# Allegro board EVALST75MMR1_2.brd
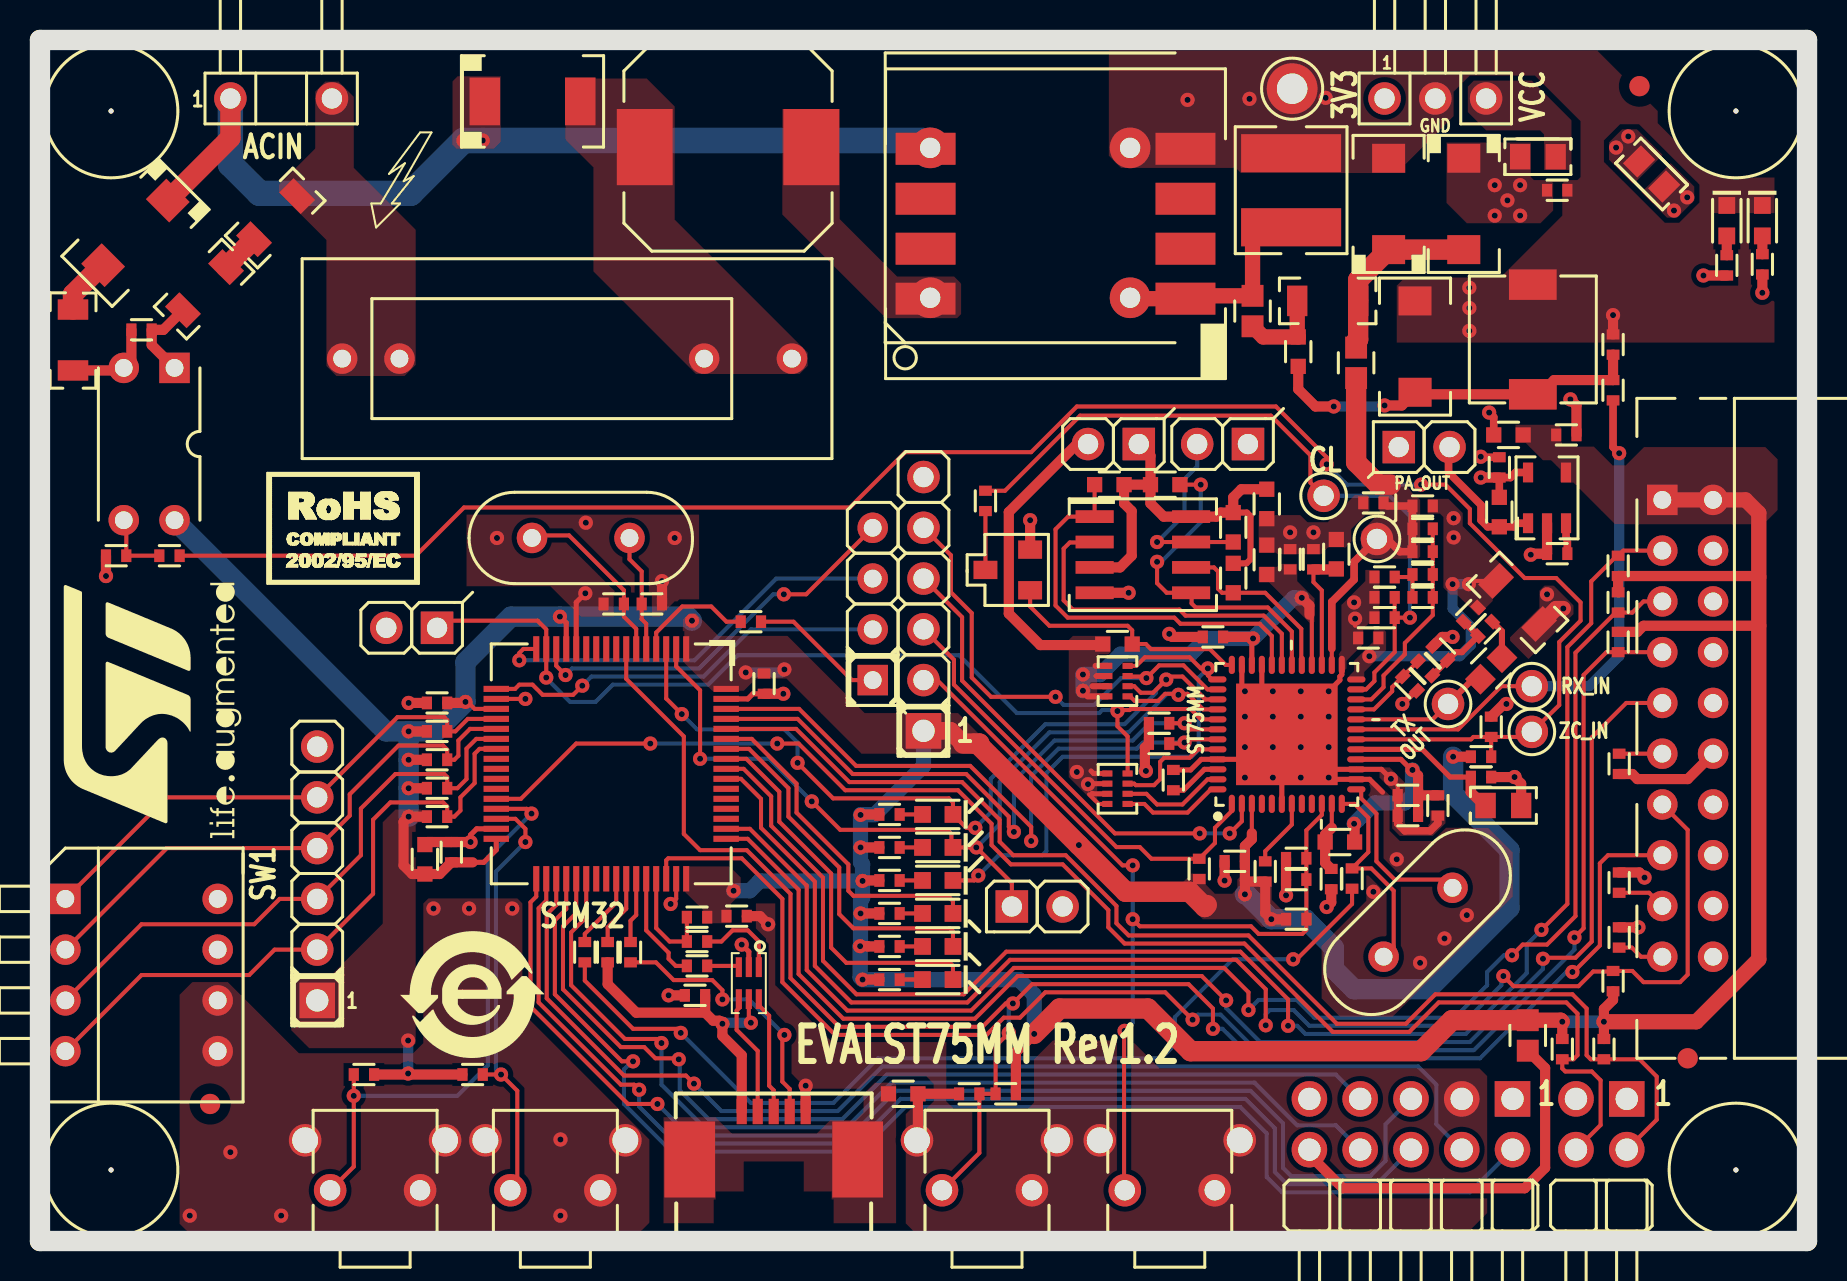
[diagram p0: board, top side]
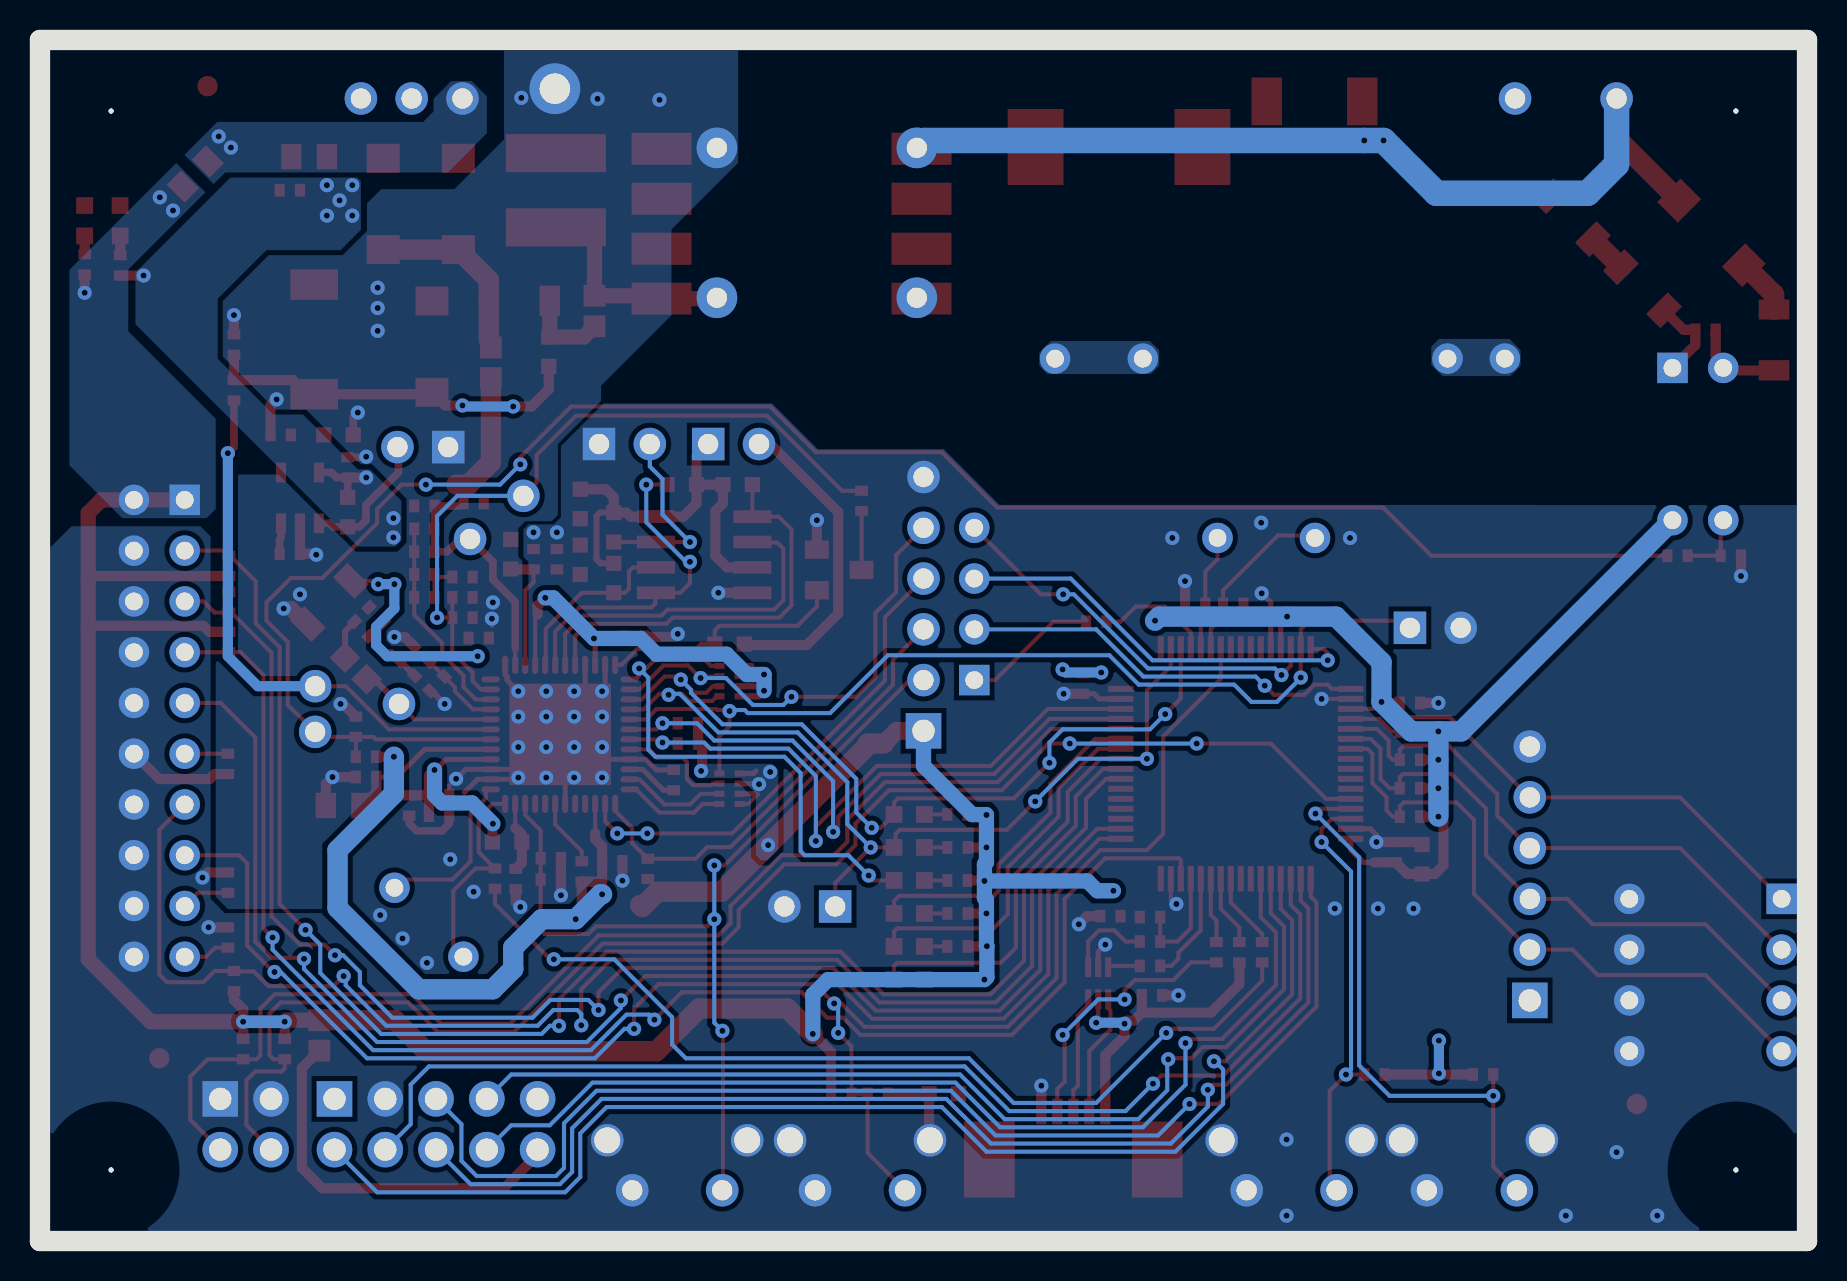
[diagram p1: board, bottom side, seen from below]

Outline 88.39 x 60.1 mm; copper layers: TOP, BOTTOM. Coordinates in mm from the lower left corner of the outline.
Outline path: 0,60.1 88.39,60.1 88.39,0 0,0 0,60.1

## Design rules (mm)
net group PRIMARIO: nets L N N19516233 N19516279 N19516280 N19534232 N195512301 PRI
net group SECONDARIO: nets 8MHZ_MCO /HOLD BOOT1/TX_ON BOOT_0 BOOT_1 CL CL_SEL I2C/UART J_TCK J_TDI J_TDO J_TMS J_TRSTN M25_C M25_D M25_Q M25_SN N19516014 N19516015 N19516212 N19516217 N19516236 N19516243 N19516257 N19558802 N19595384 N19595391 N19717143 N19717153 N19717271 N19719840 N19719859 N19719905 N19719927 N19719929 N19719997 N19720003 N19720009 N19720046 N19720048 N19720062 N19720066 N19720070 N19720108 N19726409 N19726413 N19741938 N19741958 N19741995 N19742827 N19754951 N19754973 N19761232 N19768553 N19768555 N19777479 N19777489 N197853990 PA_IN+ PA_IN- PA_OUT PLC_RESETN PLC_RESETN_UC PLC_RXD PLC_TXD RESERVED1 RESERVED2 RESERVED3 RX_IN RXD SCL SDA SEC SPI2_MISO SPI2_MOSI SPI2_NSS SPI2_SCLK STM32_CFG0 STM32_CFG1 STM32_CFG2 STM32_CFG3 STM32_NRST STM32_USB+ STM32_USB- STPM_LED STPM_SYN T_REQ T_REQ_UC TCK TX_OUT TXD USB_ID USB_VBUS VCCA VDD_1 VDD_2 VDD_PLL VDD_REG_1V8 VDDIO_FLASH ZC_IN

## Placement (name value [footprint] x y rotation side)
C1  100nF/25V/X5R  [CAPC-0402]  75.9 52.58 0 top
C2  10uF/25V/X7R  [CAPC-1206]  64.41 47.04 180 top
C4  NC  [CAPP-180X85-P15]  25.6 44.15 180 top
C5  220nF X1  [CAPP-265X100X165-P225]  26.37 44.15 180 top
C6  4.7pF/C0G  [CAPC-0402]  69.16 34.49 180 top
C7  10uF/6.3V  [CAPC-0603]  64.85 34.37 90 top
C9  100nF/X5R  [CAPC-0402]  62.53 34.11 90 top
C10  100nF/X5R  [CAPC-0402]  63.7 34.11 90 top
C11  4.7nF/25V/X7R  [CAPC-0402]  78.69 44.86 270 top
C12  12pF/C0G  [CAPC-0402]  69.16 33.35 0 top
C13  100nF/16V/X7R  [CAPC-0402]  67.26 33.22 0 top
C14  10uF/25V/X5R  [CAPC-1206]  73.91 31.95 315 top
C15  100nF  [CAPC-0402]  6.48 34.29 180 top
C16  10uF/6.3V  [CAPC-0603]  61.37 34.09 90 top
C18  100pF/C0G  [CAPC-0402]  67.26 31.19 180 top
C19  100nF/X5R  [CAPC-0402]  58.67 30.23 180 top
C20  10nF/16V/X7R  [CAPC-0402]  78.69 42.57 90 top
C21  100nF/25V/X5R  [CAPC-0402]  66.45 30.18 180 top
C22  100nF/16V/X7R  [CAPC-0402]  72.29 30.63 225 top
C23  1nF/C0G  [CAPC-0402]  68.53 27.89 135 top
C24  20pF  [CAPC-0402]  28.7 31.88 180 top
C25  20pF  [CAPC-0402]  30.61 31.88 0 top
C26  100nF  [CAPC-0402]  19.86 26.92 180 top
C27  100nF/X5R  [CAPC-0402]  72.09 23.22 0 top
C28  100nF/X5R  [CAPC-0402]  56.69 23.06 90 top
C29  1nF/X5R  [CAPC-0402]  68.43 22.3 180 top
C30  10uF/6.3V  [CAPC-0603]  73.46 40.34 180 top
C31  100nF/25V  [CAPC-0402]  76.35 40.34 0 top
C32  100nF/25V  [CAPC-0402]  75.9 34.39 180 top
C33  4.7uF/4V/X5R  [CAPC-0402]  69.93 21.79 270 top
C34  100nF/X5R  [CAPC-0402]  36.22 27.89 270 top
C37  10uF/10V/X5R  [CAPC-0805]  73.2 21.79 0 top
C38  10nF/X5R  [CAPC-0402]  68.43 21.29 180 top
C39  100nF/25V  [CAPC-0402]  73 38.71 90 top
C40  100nF  [CAPC-0603]  61.37 36.88 270 top
C41  100nF/X5R  [CAPC-0402]  62.84 19.15 180 top
C42  100nF/X5R  [CAPC-0402]  59.77 19 180 top
C43  100nF/X5R  [CAPC-0402]  64.59 18.11 270 top
C45  100nF  [CAPC-0402]  20.57 19.46 90 top
C46  10uF/6.3V  [CAPC-0603]  19.25 19.1 90 top
C48  100nF/X5R  [CAPC-0402]  34.85 16.26 0 top
C49  100nF  [CAPC-0402]  32.77 12.29 180 top
C50  100nF/X5R  [CAPC-0402]  46.48 7.37 180 top
CN1  CON-MOLEX-KK100-3PNO2  [CON-MOLEX-42376-90-3-NO2]  12.06 57.17 0 top
CN2  CON-MOLEX-KK100-3P  [CON-MOLEX-42376-90-3]  69.8 57.17 0 top
CN4  CN-USB  [USBMB-HRS-UX60SC]  36.7 0.38 0 top
D1  SM6T15CA  [DIODO-DO214AA-SMB]  24.64 57.02 0 top
D2  STPS1L30A  [DIODO-DO214AC-SMA]  67.46 51.89 90 top
D3  STPS1L30A  [DIODO-DO214AC-SMA]  71.22 51.89 270 top
D4  STTH1L06A  [DIODO-DO214AC-SMA]  4.78 50.44 225 top
D5  SMAJ5.0CA  [DIODO-DO214AC-SMA-BIDIR]  68.78 44.75 270 top
DL1  LED-RED  [LEDC-0603]  84.38 51.05 270 top
DL2  LED-GREEN  [LEDC-0603]  86.16 51.05 270 top
DL3  LED-GREEN  [LEDC-0603]  44.91 21.34 180 top
DL4  LED-RED  [LEDC-0603]  44.91 19.69 180 top
DL5  LED-GREEN  [LEDC-0603]  44.91 16.39 180 top
DL6  LED-YELLOW  [LEDC-0603]  44.91 14.74 180 top
DL7  LED-RED  [LEDC-0603]  44.91 13.08 180 top
DL8  LED-BLUE  [LEDC-0603]  44.91 18.04 180 top
FB1  BLM18AG331SN1D  [INDC-0603]  65.02 19.96 180 top
FB2  BLM18AG331SN1D  [INDC-0603]  43.18 7.37 0 top
FB3  BLM21PG331SN1  [INDC-0805]  80.62 53.39 135 top
FB4  BLM21PG331SN1  [INDC-0805]  74.93 54.25 180 top
ISO1  TLP781(GB)  [DIP254P-50X76-4]  5.46 39.88 270 top
J1  STPMx  [STRIP254P-M-5X2-90]  68.58 5.84 90 top
J2  SPI2 CONNECTOR  [STRIP254P-M-6]  13.87 18.39 180 top
JP1  CLOSE  [JP2SO]  60.66 46.53 90 top
JP2  CLOSE  [JP2SO]  65.84 43.94 90 top
JP4  CLOSE  [JP2SO]  72.59 28.65 45 top
JP5  CLOSE  [STRIP254P-M-2]  53.7 39.88 270 top
JP6  CLOSE  [STRIP254P-M-2]  59.16 39.88 270 top
JP7  -  [STRIP254P-M-6]  44.2 31.88 180 top
JP8  -  [STRIP254P-M-4]  41.66 31.88 180 top
JP9  CLOSE  [JUMP254P-M-2]  69.24 39.73 90 top
JP10  OPEN  [JP2SO]  74.42 10.29 90 top
JP11  STM32 BOOT CONFIG  [JUMP254P-M-2X2-90]  78.11 5.84 90 top
JP12  CLOSE  [STRIP254P-M-2]  18.59 30.68 270 top
JP13  CLOSE  [STRIP254P-M-2]  49.89 16.74 90 top
JTAG1  JTAG_20P  [CON-FLAT10X2-90M]  82.42 25.65 180 top
L1  B82464G4-6.8uH  [INDC-EPCOS-B82464G4]  34.42 54.74 180 top
L2  NC  [INDC-BOURNS-SDR0503]  62.59 52.58 270 top
L3  B82462G4224M000  [INDC-EPCOS-B82462A4]  74.68 45.11 270 top
NOREF  -  []  -2.79 -51.18 0 top
NOREF#2  -  []  -52.22 -87.17 0 top
NOREF#3  -  []  -40.89 -133.4 0 top
NOREF#4  -  [unnamed#2]  82.42 9.14 0 top
NOREF#5  -  [unnamed#2]  3.56 56.54 0 top
NOREF#6  -  []  0 60.07 0 top
NOREF#7  -  [unnamed#2]  8.51 6.86 0 top
NOREF#8  -  []  0 0 90 top
NOREF#9  -  [unnamed#2]  80.01 57.78 0 top
NOREF#10  -  []  9.86 19.86 90 top
NOREF#11  -  []  21.39 12.19 0 top
NOREF#12  -  []  -83.78 -202.47 0 top
NOREF#13  -  [unnamed#2]  84.84 56.54 0 top
NOREF#14  -  []  83.19 -9.02 0 top
NOREF#15  -  [unnamed#2]  3.56 3.56 0 top
NOREF#16  -  []  42.21 -145.9 0 top
NOREF#17  -  [unnamed#2]  84.84 3.56 0 top
Q1  2N7002  [SOT23]  48.41 33.58 90 top
R1  33K  [RESC-1206]  11.79 51.21 45 top
R2  33K  [RESC-1206]  8.23 47.65 45 top
R3  3K9  [RESC-0402]  84.38 48.82 90 top
R4  470R  [RESC-0402]  86.16 48.87 90 top
R5  100R  [RESC-0603]  62.94 44.5 90 top
R6  100k  [RESC-0402]  5.08 45.59 180 top
R7  33K  [RESC-1206]  1.65 45.09 90 top
R9  24K  [RESC-0402]  66.7 36.93 180 top
R12  24K  [RESC-0402]  69.16 36.78 0 top
R13  27K  [RESC-0402]  69.16 35.64 0 top
R15  10K  [RESC-0402]  78.94 33.78 90 top
R16  47K  [RESC-0402]  3.81 34.29 0 top
R17  130R  [RESC-0402]  67.26 32.21 180 top
R18  10K  [RESC-0402]  69.16 32.21 0 top
R20  10K  [RESC-0402]  78.94 31.95 270 top
R21  47K  [RESC-0402]  71.58 31.34 45 top
R26  47K  [RESC-0402]  70.05 29.41 315 top
R27  0R  [RESC-0402]  69.29 28.65 135 top
R29  10K  [RESC-0402]  78.94 29.97 270 top
R30  10M  [RESC-0402]  72.59 25.73 270 top
R32  4K7  [RESC-0402]  35.56 30.99 180 top
R33  NC  [RESC-0402]  72.09 24.23 180 top
R34  10K  [RESC-0402]  78.99 23.88 270 top
R36  100K  [RESC-0603]  73 36.47 270 top
R38  4k7  [RESC-0603]  59.69 33.17 270 top
R39  4k7  [RESC-0603]  53.49 37.85 180 top
R40  4k7  [RESC-0603]  56.29 37.85 0 top
R41  10K  [RESC-0402]  57.99 18.62 270 top
R42  10K  [RESC-0402]  61.29 18.49 270 top
R43  0R  [RESC-0402]  65.63 18.14 90 top
R44  100k  [RESC-0402]  62.84 18.08 0 top
R45  NC  [RESC-0402]  62.84 16.1 180 top
R46  10K  [RESC-0402]  19.86 25.5 180 top
R47  560R  [RESC-0402]  42.5 21.34 180 top
R48  10K  [RESC-0402]  19.86 24.08 180 top
R49  10K  [RESC-0402]  78.99 17.93 90 top
R50  330R  [RESC-0402]  47.29 37.03 90 top
R51  560R  [RESC-0402]  42.5 19.69 180 top
R52  10K  [RESC-0402]  78.99 15.19 90 top
R53  10k  [RESC-0603]  53.9 29.87 180 top
R54  10K  [RESC-0402]  19.86 22.66 180 top
R55  470R  [RESC-0402]  42.5 16.39 0 top
R56  4K7  [RESC-0402]  55.98 25.91 0 top
R57  4K7  [RESC-0402]  55.98 24.89 0 top
R58  1K5  [RESC-0402]  32.87 16.21 0 top
R59  470R  [RESC-0402]  42.5 14.74 0 top
R60  10K  [RESC-0402]  19.86 21.23 180 top
R61  22R  [RESC-0402]  32.87 14.99 0 top
R62  0R  [RESC-0402]  27.25 14.45 270 top
R63  NC  [RESC-0402]  28.4 14.45 270 top
R64  NC  [RESC-0402]  29.54 14.45 270 top
R65  22R  [RESC-0402]  32.87 13.77 180 top
R66  470R  [RESC-0402]  42.5 13.08 0 top
R67  10K  [RESC-0402]  78.69 13 90 top
R68  10K  [RESC-0402]  16.21 8.33 0 top
R69  10K  [RESC-0402]  21.64 8.33 180 top
R70  10K  [RESC-0402]  76.15 9.6 270 top
R71  10K  [RESC-0402]  78.23 9.6 270 top
R74  10K  [RESC-0402]  48.31 7.37 0 top
R75  4k7  [RESC-0603]  59.69 35.71 270 top
R76  560R  [RESC-0402]  42.5 18.04 180 top
RN2  10K  [RESN-CAY10]  53.9 28.02 0 top
RN3  10K  [RESN-CAY10]  53.9 22.63 0 top
SW1  DIPSW-4P-90  [DIPSW254P-4P-90]  5.08 13.31 270 top
SW2  PUSH_1  [BUTTON-6X6-PTH-90]  16.76 2.54 0 top
SW3  PUSH_2  [BUTTON-6X6-PTH-90]  25.78 2.54 0 top
SW4  STM32 RESET  [BUTTON-6X6-PTH-90]  47.37 2.54 0 top
SW5  ST75MM RESET  [BUTTON-6X6-PTH-90]  56.52 2.54 0 top
T1  WE 750-510-231  [TRAFO-TDK-SRW13EP]  49.53 52.2 90 top
T1A  TDK SRW13EP-X07S002  [TRAFO-TDK-SRW13EP-X07]  50.8 50.9 180 top
TP1  CL  [TPTH-ANELLO-1MM]  64.21 37.29 0 top
TP2  PA_OUT  [TPTH-ANELLO-1MM]  66.88 35.13 0 top
TP6  RX_IN  [TPTH-ANELLO-1MM]  74.63 27.76 315 top
TP8  TX_OUT  [TPTH-ANELLO-1MM]  70.43 26.87 0 top
TP11  ZC_IN  [TPTH-ANELLO-1MM]  74.63 25.48 0 top
TP13  VSS  [TPTH-PERNO-13MM]  62.64 57.66 0 top
U2  ST75MM  [QFN50P700X700X80-49N]  62.37 25.35 90 top
U3  STM32F103RGT7  [QFP050P-1200X1200X160-64]  28.57 23.88 270 top
U4  LK112SM33TR  [SOT23-5]  75.39 37.19 0 top
U5  USBLC6-2P6  [SOT-666]  35.46 12.9 180 top
U6  M25P10-A  [SOP127P-620X168-8]  55.17 34.34 0 top
Y1  8MHz  [XTAL-HC49U]  27.05 35.18 0 top
Y2  NC  [XTAL-HC49U]  68.94 15.95 225 top

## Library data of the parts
C1 C2 C6 C7 C9-C13 C15 C16 C18-C34 C37-C39 C41-C43 C45 C46 C48-C50 = CAPC-SMD
C4 C5 C14 = CAPC-1206
C40 = CAP NP
CN1 = CON-MOLEX-KK100-3PNO2
CN2 = CON-MOLEX-KK100-3P
CN4 = USBMB-HRS-UX60SC
D1 = DIODE DIAC_0
D2 D3 = DIODO-STPS1L30A
D4 = DIODO-STTH1L06A-SMA
D5 = DIODO-SMAJCA-SMA_0
DL1-DL8 = LEDC-0603
FB1 FB2 = BID-0603
FB3 FB4 = BID-0805
ISO1 = OPTO ISOLATOR-A_0
J1 = STRIP254P-M-5x2
J2 JP7 = STRIP254P-M-6
JP1 JP2 JP4 JP10 = JP2SO
JP5 JP6 JP12 JP13 = JUMPER
JP8 = STRIP254P-M-4
JP9 = JUMP254P-M-2
JP11 = JUMP254P-M-2x2-90
JTAG1 = CON-FLAT-10X2
L1 L3 = INDC-EPCOS-B82464G4
L2 = INDC-BOURNS-SDR0503
Q1 = MOS-2N7002-SOT23
R1-R7 R9 R12 R13 R15-R18 R20 R21 R26 R27 R29 R30 R32-R34 R36 R41-R71 R74 R76 = RESC-SMD
R38-R40 R75 = R
RN2 RN3 = RESN-CAY10
SW1 = DIPSW-CEK-SDA04HXBD
SW2-SW5 = PULSANTE-6X6MM-90
T1 = TRAFO-TDK-SRW13EP
T1A = TRAFO-TDK-SRW13EP-X07S002
TP1 TP2 TP6 TP8 TP11 = TPTH-ANELLO-1MM
TP13 = TPTH-PERNO-13MM
U2 = IC-ST7590-QFN48_2
U3 = IC-STM32-LQFP64
U4 = IC-LK112SXX-SOT23-5
U5 = IC-USBLC6-2P6_1
U6 = M25P10_3
Y1 Y2 = CRYSTAL

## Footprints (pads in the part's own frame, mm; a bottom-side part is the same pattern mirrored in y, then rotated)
BUTTON-6X6-PTH-90
  round 1.626 hole 1.016: 1(-2.25,0) 2(2.25,0)
  round 1.626 hole 1.295: SH1(-3.5,2.5) SH2(3.5,2.5)
CAPC-0402
  rect 0.508x0.635 smd: 1(-0.508,0) 2(0.508,0)
CAPC-0603
  rect 0.762x0.762 smd: 1(-0.737,0) 2(0.737,0)
CAPC-0805
  rect 1.016x1.27 smd: 1(-0.889,0) 2(0.889,0)
CAPC-1206
  rect 1.016x1.524 smd: 1(-1.524,0) 2(1.524,0)
CAPP-180X85-P15
  round 1.524 hole 0.889: 1(-7.62,0) 2(7.62,0)
CAPP-265X100X165-P225
  round 1.524 hole 0.889: 1(-11.25,0) 2(11.25,0)
CON-FLAT10X2-90M
  rect 1.524x1.524 hole 0.889: 1(1.27,-11.43)
  round 1.524 hole 0.889: 2(-1.27,-11.43) 3(1.27,-8.89) 4(-1.27,-8.89) 5(1.27,-6.35) 6(-1.27,-6.35) 7(1.27,-3.81) 8(-1.27,-3.81) 9(1.27,-1.27) 10(-1.27,-1.27) 11(1.27,1.27) 12(-1.27,1.27) 13(1.27,3.81) 14(-1.27,3.81) 15(1.27,6.35) 16(-1.27,6.35) 17(1.27,8.89) 18(-1.27,8.89) 19(1.27,11.43) 20(-1.27,11.43)
CON-MOLEX-42376-90-3
  round 1.626 hole 1.016: 1(-2.54,0) 2(0,0) 3(2.54,0)
CON-MOLEX-42376-90-3-NO2
  round 1.626 hole 1.016: 1(-2.54,0) 3(2.54,0)
DIODO-DO214AA-SMB
  rect 1.524x2.388 smd: 1(-2.388,0) 2(2.388,0)
DIODO-DO214AC-SMA
  rect 1.448x1.651 smd: 1(-2.286,0) 2(2.286,0)
DIODO-DO214AC-SMA-BIDIR
  rect 1.448x1.651 smd: 1(-2.286,0) 2(2.286,0)
DIP254P-50X76-4
  rect 1.524x1.524 hole 0.889: 1(-3.81,1.27)
  round 1.524 hole 0.889: 2(-3.81,-1.27) 3(3.81,-1.27) 4(3.81,1.27)
DIPSW254P-4P-90
  rect 1.524x1.524 hole 0.889: 1(-3.81,-3.81)
  round 1.524 hole 0.889: 2(-1.27,-3.81) 3(1.27,-3.81) 4(3.81,-3.81) 5(3.81,3.81) 6(1.27,3.81) 7(-1.27,3.81) 8(-3.81,3.81)
INDC-0603
  rect 0.762x0.762 smd: 1(-0.737,0) 2(0.737,0)
INDC-0805
  rect 1.016x1.27 smd: 1(-0.889,0) 2(0.889,0)
INDC-BOURNS-SDR0503
  rect 1.905x5.004 smd: 1(-1.854,0) 2(1.854,0)
INDC-EPCOS-B82462A4
  rect 1.524x2.388 smd: 1(-2.743,0) 2(2.743,0)
INDC-EPCOS-B82464G4
  rect 2.794x3.81 smd: 1(-4.166,0) 2(4.166,0)
JP2SO
  rect 1.092x1.092 smd: 1(-0.762,0) 2(0.762,0)
JUMP254P-M-2
  rect 1.626x1.626 hole 1.016: 1(0,1.27)
  round 1.626 hole 1.016: 2(0,-1.27)
JUMP254P-M-2X2-90
  rect 1.778x1.778 hole 1.118: 1(1.27,-1.27)
  round 1.778 hole 1.118: 2(-1.27,-1.27) 3(1.27,1.27) 4(-1.27,1.27)
LEDC-0603
  rect 0.838x0.838 smd: 1(-0.762,0) 2(0.762,0)
QFN50P700X700X80-49N
  oval 0.914x0.305 smd: 1(-3.477,2.75) 2(-3.477,2.25) 3(-3.477,1.75) 4(-3.477,1.25) 5(-3.477,0.75) 6(-3.477,0.25) 7(-3.477,-0.25) 8(-3.477,-0.75) 9(-3.477,-1.25) 10(-3.477,-1.75) 11(-3.477,-2.25) 12(-3.477,-2.75) 25(3.477,-2.75) 26(3.477,-2.25) 27(3.477,-1.75) 28(3.477,-1.25) 29(3.477,-0.75) 30(3.477,-0.25) 31(3.477,0.25) 32(3.477,0.75) 33(3.477,1.25) 34(3.477,1.75) 35(3.477,2.25) 36(3.477,2.75)
  oval 0.305x0.914 smd: 13(-2.75,-3.477) 14(-2.25,-3.477) 15(-1.75,-3.477) 16(-1.25,-3.477) 17(-0.75,-3.477) 18(-0.25,-3.477) 19(0.25,-3.477) 20(0.75,-3.477) 21(1.25,-3.477) 22(1.75,-3.477) 23(2.25,-3.477) 24(2.75,-3.477) 37(2.75,3.477) 38(2.25,3.477) 39(1.75,3.477) 40(1.25,3.477) 41(0.75,3.477) 42(0.25,3.477) 43(-0.25,3.477) 44(-0.75,3.477) 45(-1.25,3.477) 46(-1.75,3.477) 47(-2.25,3.477) 48(-2.75,3.477)
  rect 5.08x5.08 smd: 49(0,0)
QFP050P-1200X1200X160-64
  rect 1.27x0.305 smd: 1(-5.75,3.75) 2(-5.75,3.25) 3(-5.75,2.75) 4(-5.75,2.25) 5(-5.75,1.75) 6(-5.75,1.25) 7(-5.75,0.75) 8(-5.75,0.25) 9(-5.75,-0.25) 10(-5.75,-0.75) 11(-5.75,-1.25) 12(-5.75,-1.75) 13(-5.75,-2.25) 14(-5.75,-2.75) 15(-5.75,-3.25) 16(-5.75,-3.75) 33(5.75,-3.75) 34(5.75,-3.25) 35(5.75,-2.75) 36(5.75,-2.25) 37(5.75,-1.75) 38(5.75,-1.25) 39(5.75,-0.75) 40(5.75,-0.25) 41(5.75,0.25) 42(5.75,0.75) 43(5.75,1.25) 44(5.75,1.75) 45(5.75,2.25) 46(5.75,2.75) 47(5.75,3.25) 48(5.75,3.75)
  rect 0.305x1.27 smd: 17(-3.75,-5.75) 18(-3.25,-5.75) 19(-2.75,-5.75) 20(-2.25,-5.75) 21(-1.75,-5.75) 22(-1.25,-5.75) 23(-0.75,-5.75) 24(-0.25,-5.75) 25(0.25,-5.75) 26(0.75,-5.75) 27(1.25,-5.75) 28(1.75,-5.75) 29(2.25,-5.75) 30(2.75,-5.75) 31(3.25,-5.75) 32(3.75,-5.75) 49(3.75,5.75) 50(3.25,5.75) 51(2.75,5.75) 52(2.25,5.75) 53(1.75,5.75) 54(1.25,5.75) 55(0.75,5.75) 56(0.25,5.75) 57(-0.25,5.75) 58(-0.75,5.75) 59(-1.25,5.75) 60(-1.75,5.75) 61(-2.25,5.75) 62(-2.75,5.75) 63(-3.25,5.75) 64(-3.75,5.75)
RESC-0402
  rect 0.508x0.635 smd: 1(-0.508,0) 2(0.508,0)
RESC-0603
  rect 0.762x0.762 smd: 1(-0.737,0) 2(0.737,0)
RESC-1206
  rect 1.016x1.524 smd: 1(-1.524,0) 2(1.524,0)
RESN-CAY10
  rect 0.508x0.305 smd: 1(-0.508,0.762) 2(-0.508,0.254) 3(-0.508,-0.254) 4(-0.508,-0.762) 5(0.508,-0.762) 6(0.508,-0.254) 7(0.508,0.254) 8(0.508,0.762)
SOP127P-620X168-8
  rect 1.905x0.635 smd: 1(-2.413,1.905) 2(-2.413,0.635) 3(-2.413,-0.635) 4(-2.413,-1.905) 5(2.413,-1.905) 6(2.413,-0.635) 7(2.413,0.635) 8(2.413,1.905)
SOT23
  rect 0.914x1.194 smd: 1(-1.016,-1.118) 2(1.016,-1.118) 3(0,1.118)
SOT23-5
  rect 0.508x0.991 smd: 1(-0.95,-1.27) 2(0,-1.27) 3(0.95,-1.27) 4(0.95,1.27) 5(-0.95,1.27)
SOT-666
  rect 0.305x0.991 smd: 1(-0.5,-0.8) 2(0,-0.8) 3(0.5,-0.8) 4(0.5,0.8) 5(0,0.8) 6(-0.5,0.8)
STRIP254P-M-2
  rect 1.626x1.626 hole 1.016: 1(0,1.27)
  round 1.626 hole 1.016: 2(0,-1.27)
STRIP254P-M-4
  rect 1.524x1.524 hole 0.889: 1(0,3.81)
  round 1.524 hole 0.889: 2(0,1.27) 3(0,-1.27) 4(0,-3.81)
STRIP254P-M-5X2-90
  rect 1.778x1.778 hole 1.118: 1(1.27,-5.08)
  round 1.778 hole 1.118: 2(-1.27,-5.08) 3(1.27,-2.54) 4(-1.27,-2.54) 5(1.27,0) 6(-1.27,0) 7(1.27,2.54) 8(-1.27,2.54) 9(1.27,5.08) 10(-1.27,5.08)
STRIP254P-M-6
  rect 1.778x1.778 hole 1.118: 1(0,6.35)
  round 1.626 hole 1.016: 2(0,3.81) 3(0,1.27) 4(0,-1.27) 5(0,-3.81) 6(0,-6.35)
TPTH-ANELLO-1MM
  round 1.626 hole 1.016: 1(0,0)
TPTH-PERNO-13MM
  round 2.54 hole 1.524: 1(0,0)
TRAFO-TDK-SRW13EP
  round 2.032 hole 1.016: 1(-5,5) 4(2.5,5) 7(2.5,-5) 10(-5,-5)
TRAFO-TDK-SRW13EP-X07
  rect 2.997x1.6 smd: 1(-6.5,3.75) 2(-6.5,1.25) 3(-6.5,-1.25) 4(-6.5,-3.75) 5(6.5,-3.75) 6(6.5,-1.25) 7(6.5,1.25) 8(6.5,3.75)
unnamed#2
  round 1.016 smd: (0,0)
USBMB-HRS-UX60SC
  rect 0.508x1.27 smd: 1(-1.6,6.1) 2(-0.8,6.1) 3(0,6.1) 4(0.8,6.1) 5(1.6,6.1)
  rect 2.54x3.81 smd: SH1(-4.2,3.7) SH2(4.2,3.7)
XTAL-HC49U
  round 1.524 hole 0.889: 1(-2.438,0) 2(2.438,0)

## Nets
GND_FIELD SIGNAL: C1.2 C7.2 C9.2 C10.2 C11.1 C13.1 C14.2 C16.2 C18.2 C19.2 C21.2 C23.1 C24.2 C25.2 C26.2 C27.2 C28.2 C29.2 C30.2 C31.2 C32.2 C33.2 C34.2 C37.2 C38.2 C39.2 C40.2 C41.2 C42.2 C43.2 C45.2 C46.2 C48.2 C49.2 C50.2 CN2.2 CN4.5 D2.2(A) D5.1 DL1.1(CATHODE) DL2.1(CATHODE) FB2.2 J1.3 J2.6 JP6.1 JP7.6 JP9.1 JP11.1 JP11.3 JP12.2 JP13.2 JTAG1.4 JTAG1.6 JTAG1.8 JTAG1.10 JTAG1.12 JTAG1.14 JTAG1.16 JTAG1.18 JTAG1.20 L2.1 L3.1 Q1.2(S) R9.2 R16.1 R17.2 R26.1 R30.1 R34.2 R44.1 R49.2 R52.2 SW1.5(B4) SW1.6(B3) SW1.7(B2) SW1.8(B1) SW2.2 SW2.SH1(3) SW2.SH2(4) SW3.2 SW3.SH1(3) SW3.SH2(4) SW4.2 SW4.SH1(3) SW4.SH2(4) SW5.2 SW5.SH1(3) SW5.SH2(4) T1.7 T1A.4 TP13.1 U2.6(GND#6) U2.14(GND#14) U2.15(VSSA) U2.25(VSS) U2.33(GND#33) U2.35(RES0) U2.45(GND#45) U2.49(EP) U3.12(VSSA) U3.18(VSS4) U3.31(VSS1) U3.47(VSS2) U3.63(VSS3) U4.2(GND) U5.2(GND) U6.4(VSS)
VCC: C1.1 C14.1 C21.1 C39.1 D3.1(K) FB4.2 R3.1 R12.2 R21.2 R36.1 U2.24(VCC) U4.5(IN)
VCCA: C27.1 C37.1 U2.17(VCCA)
VDD_1: C28.1 U2.46(VDD#46)
VDD_2: C43.1 FB1.2 U2.11(VDD#11)
VDD_PLL: C29.1 C33.1 C38.1 FB1.1 U2.16(VDD_PLL)
VDD_REG_1V8: C7.1 C10.1 U2.27(VDD_REG_1V8)
VDDIO: C9.1 C16.1 C19.1 C26.1 C30.1 C31.1 C34.1 C42.1 C45.1 C46.1 C48.1 FB3.1 ISO1.4(COLLECTOR) J2.1 JP5.2 JP7.1 JP10.2 JTAG1.1 JTAG1.2 R4.1 R15.1 R20.1 R29.1 R33.2 R41.2 R42.2 R45.2 R46.2 R47.2 R48.2 R51.2 R53.2 R54.2 R55.1 R56.1 R57.1 R58.2 R59.1 R60.2 R66.1 R67.1 R68.2 R69.2 R70.1 R71.1 R74.2 R76.2 RN2.1 RN2.2 RN2.3 RN2.4 RN3.1 RN3.2 RN3.3 RN3.4 U2.3(VDDIO#3) U2.28(VDDIO_FLASH) U2.34(VDDIO#34) U3.1(VBAT) U3.13(VDDA) U3.19(VDD4) U3.32(VDD1) U3.48(VDD2) U3.64(VDD3) U4.4(OUT)
VDDIO_FLASH: C40.1 JP5.1 R38.1 R39.1 R40.1 R75.1 U6.3(/W) U6.8(VCC)
8MHZ_MCO: R43.1 R62.2
/HOLD: JP6.2 R75.2 U6.7(/HOLD)
BIU/PHY_ACT: DL8.1(CATHODE) RN2.8 U2.37(BIU/PHY_ACT)
BOOT0/PHY_ACT: DL4.1(CATHODE) JP13.1 RN2.5 U2.40(BOOT0/PHY_ACT) U3.2(PC13/TAMP/RTC)
BOOT1/TX_ON: DL3.1(CATHODE) RN2.6 U2.39(BOOT1) U3.3(PC14/OSC32-IN)
BOOT_0: JP11.2 R71.2 U3.60(BOOT0)
BOOT_1: JP11.4 R70.2 U3.28(PB2)
CL: C18.1 R17.1 R50.2 TP1.1 U2.23(CL)
CL_SEL: Q1.1(G) R53.1 U2.36(CL_SEL)
I2C/UART: JP12.1 RN3.8 U2.41(I2C/UART) U3.15(PA1)
J_TCK: JTAG1.9 U3.49(PA14)
J_TDI: JTAG1.5 R20.2 U3.50(PA15)
J_TDO: JTAG1.13 R67.2 U3.55(PB3)
J_TMS: JTAG1.7 R29.2 U3.46(PA13)
J_TRSTN: JTAG1.3 R15.2 U3.56(PB4)
L: C4.2 C5.2 CN1.3 R1.2
M25_C: R38.2 U2.29(M25_C) U6.6(C)
M25_D: R40.2 U2.30(M25_D) U6.5(D)
M25_Q: U2.31(M25_Q) U6.2(Q)
M25_SN: R39.2 U2.32(M25_SN) U6.1(/S)
N: CN1.1 D1.1 D4.1(K) T1.4 T1A.5
PA_IN+: C23.2 R27.2 U2.21(PA_IN_P)
PA_IN-: C6.1 C12.2 R13.2 R18.2 U2.22(PA_IN_N)
PA_OUT: C6.2 JP2.1 R9.1 R12.1 R13.1 TP2.1 U2.26(PA_OUT)
PLC_RESETN: C41.1 JP7.2 R44.2 R45.1 SW5.1 U2.10(RESETN)
PLC_RESETN_UC: JP8.1 R32.1
PLC_RXD: JP8.2 U3.17(PA3)
PLC_TXD: JP8.3 U3.16(PA2)
PRI: L1.1 T1.1 T1A.8
RESERVED1: RN3.7 U2.44(RES1)
RESERVED2: RN3.6 U2.47(RES2)
RESERVED3: RN3.5 U2.48(RES3)
RX_IN: C20.1 TP6.1 U2.19(RX_IN)
RXD: JP7.4 U2.2(RXD)
SCL: R56.2 U2.42(SCL) U3.61(PB8)
SDA: R57.2 U2.43(SDA) U3.62(PB9)
SEC: JP1.2 L2.2 T1.10 T1A.1
SPI2_MISO: J1.4 U3.35(PB14)
SPI2_MOSI: J1.2 U3.36(PB15)
SPI2_NSS: J1.5 U3.33(PB12)
SPI2_SCLK: J1.6 U3.34(PB13)
STM32_CFG0: J2.5 R46.1 SW1.1(A1) U3.20(PA4)
STM32_CFG1: J2.4 R48.1 SW1.2(A2) U3.21(PA5)
STM32_CFG2: J2.3 R54.1 SW1.3(A3) U3.22(PA6)
STM32_CFG3: J2.2 R60.1 SW1.4(A4) U3.23(PA7)
STM32_NRST: C50.1 JTAG1.15 R74.1 SW4.1 U3.7(NRST)
STM32_USB+: R58.1 R61.1 U3.45(PA12)
STM32_USB-: R65.2 U3.44(PA11)
STPM_LED: J1.7 U3.37(PC6)
STPM_SYN: J1.8 U3.38(PC7)
T_REQ: JP7.5 RN2.7 U2.38(T_REQ)
T_REQ_UC: JP8.4 U3.14(PA0-WKUP)
TCK: R42.1 U2.7(TCK)
TX_OUT: JP4.1 TP8.1 U2.20(TX_OUT)
TXD: JP7.3 R41.1 U2.1(TXD)
USB_ID: CN4.4 R64.2
USB_VBUS: C49.1 CN4.1 R63.2 U5.5(VBUS)
ZC_IN: C15.1 R30.2 R33.1 TP11.1 U2.18(ZC_IN)
N19516014: DL3.2(ANODE) R47.1
N19516015: DL4.2(ANODE) R51.1
N19516212: C2.2 JP1.1 R5.2
N19516217: C2.1 D2.1(K) D3.2(A) JP2.2
N19516233: C4.1 C5.1 D1.2 L1.2
N19516236: C12.1 C13.2 R18.1
N19516243: C11.2 C20.2 D5.2 L3.2 R5.1
N19516257: C22.2 R21.1 R26.2 R27.1
N19516279: ISO1.2(CATHODE) R6.2 R7.1
N19516280: ISO1.1(ANODE) R2.1 R6.1
N19534232: R1.1 R2.2
N19558802: C15.2 ISO1.3(EMITTER) R16.2
N19595384: U2.13(XOUT) Y2.1
N19595391: R43.2 U2.12(XIN) Y2.2
N19717143: CN4.SH1 CN4.SH2 FB2.1
N19717153: CN4.3 U5.6(I/O1#2)
N19717271: CN4.2 U5.4(I/O2#2)
N19719840: R64.1 U3.43(PA10)
N19719859: R63.1 U3.42(PA9)
N19719905: R32.2 U3.4(PC15/OSC32-OUT)
N19719927: DL7.2(ANODE) R66.2
N19719929: DL6.2(ANODE) R59.2
N19719997: C25.1 U3.5(PD0/OSC-IN) Y1.2
N19720003: DL5.2(ANODE) R55.2
N19720009: C24.1 U3.6(PD1/OSC-OUT) Y1.1
N19720046: R68.1 SW2.1 U3.29(PB10)
N19720048: R69.1 SW3.1 U3.30(PB11)
N19720062: DL5.1(CATHODE) U3.59(PB7)
N19720066: DL6.1(CATHODE) U3.58(PB6)
N19720070: DL7.1(CATHODE) U3.57(PB5)
N19720108: R62.1 U3.41(PA8)
N19726409: DL1.2(ANODE) R3.2
N19726413: DL2.2(ANODE) R4.2
N19741938: JTAG1.19 R52.1
N19741958: JTAG1.17 R49.1
N19741995: JTAG1.11 R34.1
N19742827: J1.10 JP10.1
N19754951: CN2.3 FB4.1
N19754973: CN2.1 FB3.2
N19761232: C22.1 JP4.2
N19768553: R65.1 U5.3(I/O2#1)
N19768555: R61.2 U5.1(I/O1#1)
N19777479: C32.1 U4.3(BYPASS)
N19777489: JP9.2 R36.2 U4.1(SHDN)
N19810275: DL8.2(ANODE) R76.1
N195512301: D4.2(A) R7.2
N197853990: Q1.3(D) R50.1

Pads without a net: J1 1 9; T1A 2 3 6 7; U2 4 5 8 9; U3 8 9 10 11 24 25 26 27 39 40 51 52 53 54

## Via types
v1: diameter 0.711, hole 0.305, TOP to BOTTOM, 195 vias

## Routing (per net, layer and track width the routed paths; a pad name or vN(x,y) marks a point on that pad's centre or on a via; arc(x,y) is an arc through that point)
GND_FIELD SIGNAL: length 93.4
  TOP w0.203: C14.2 75.76,31.65 75.84,31.65 ; C29.2 67.92,22.78 v1(67.58,23.13) ; U3.47 31.82,17.12 31.55,16.84 v1(31.55,16.87) ; v1(24.28,27.13) U3.18 ; 65.79,30.78 v1(65.79,31.14)
  TOP w0.254: 64.12,23.6 v1(64.47,23.19) 64.55,23.1 U2.14 66.51,23.1 67.16,22.45 ; 64.12,23.6 U2.15 67.1,23.6 v1(67.58,23.13) ; 64.12,23.6 U2.49 ; 27.08,32.21 26.82,31.96 U3.12 ; 62.12,25.1 61.12,24.1 U2.45 58.09,24.1 57.56,23.57 C28.2 ; 62.12,25.1 U2.49 ; 62.12,25.1 U2.6 ; C34.2 35.66,27.38 35.41,27.13 U3.63 ; U2.49 61.12,26.6 ; U2.49 v1(64.47,27.51) 65.02,28.07 65.02,28.24 65.12,28.34 U2.25 ; 61.12,26.6 U2.33 ; 61.12,26.6 v1(60.27,27.51) 60.12,27.6 U2.35 ; U3.31 21.85,20.63 21.54,20.32 v1(21.54,19.96) ; U5.2 35.46,14.48 v1(35.1,14.83)
  TOP w0.305: C23.1 68.81,27.53 v1(68.15,26.87)
  TOP w0.381: C29.2 C38.2 67.92,20.88 68.28,20.52 69.55,20.52 69.93,20.9 C33.2 ; C30.2 72.72,41.22 v1(72.49,41.45) ; C39.2 72.1,39.22 v1(72.07,39.24)
  TOP w0.508: SW4.SH1 43.92,5.09 FB2.2 C50.2 ; R16.1 v1(3.3,33.27) ; R34.2 79.65,23.37 79.91,23.11 82.42,23.11 JTAG1.12 ; v1(80.26,18.19) 80.01,18.44 R49.2 ; R26.1 70.15,30.23 v1(70.66,30.23) ; C46.2 19.38,19.96 C45.2 v1(21.54,19.96) ; C49.2 v1(31.45,12.29) ; C37.2 74.09,22.89 v1(73.76,23.22) C27.2 ; v1(37.19,27.38) C34.2 ; v1(64.36,16.71) 64.59,16.94 C43.2 ; R30.1 73.23,26.87 v1(73.36,26.87) ; CN4.5 v1(38.3,7.77) ; C11.1 v1(78.69,46.33) ; v1(56.49,30.38) 56.64,30.23 C19.2 ; U4.2 C32.2 74.63,34.39 v1(74.57,34.34) ; R52.2 v1(79.96,15.7) ; v1(62.33,17.3) R44.1 C41.2 ; Q1.2 v1(49.53,36.07) ; v1(18.44,26.92) C26.2 ; v1(36.42,15.85) 36.02,16.26 C48.2 ; U6.4 v1(54.46,32.44) ; v1(76.56,42.11) 76.86,41.81 C31.2 ; C42.2 v1(59.26,18.03) ; C25.2 v1(31.11,33.02)
  TOP w0.762: v1(76.2,31.65) 75.84,31.65 75.07,30.88 C14.2 ; 54.78,54.7 T1.7
  vias: v1(7.49,1.27) v1(9.53,4.45) v1(12.06,1.27) v1(19.68,16.64) v1(21.46,16.64) v1(22.86,35.18) v1(23.62,16.64) v1(26.04,5.08) v1(26.04,1.27) v1(27.3,35.94) v1(27.28,32.41) v1(31.75,35.18) v1(57.4,57.1) v1(60.27,26.24) v1(60.27,24.71) v1(60.27,23.19) v1(60.5,57.15) v1(61.67,27.51) v1(61.67,26.24) v1(61.67,24.71) v1(61.67,23.19) v1(62.53,35.46) v1(63.07,27.51) v1(63.07,26.24) v1(63.07,24.71) v1(63.07,23.19) v1(63.7,35.46) v1(64.31,57.2) v1(64.47,26.24) v1(64.47,24.71) v1(65.74,31.95) v1(66.7,17.48) v1(67.87,19.1) v1(69.04,13.92) v1(70.26,15.14) v1(71.37,16.31) v1(71.5,47.7) v1(71.5,46.69) v1(71.5,45.54) v1(75.39,32.36)
VCC: length 15.6
  TOP w0.203: v1(71.48,32.87) 71.64,33.03 C14.1
  TOP w0.381: U4.5 73.81,38.46 73.56,38.2 C39.1 R36.1
  TOP w0.508: R3.1 v1(83.21,48.31) ; v1(72.07,38.2) C39.1
  BOTTOM w0.508: v1(66.5,29.26) 71.02,29.26 71.58,29.82 71.58,30.73 70.66,31.65 v1(70.66,32.87) v1(71.48,32.87)
  vias: v1(70.71,36.17) v1(70.71,35.2) v1(72.77,52.83) v1(72.77,51.31) v1(73.41,52.07) v1(74.04,52.83) v1(74.04,51.31)
VCCA: length 8.1
  TOP w0.254: U2.17 69.15,24.6 70.54,23.22 C27.1
  TOP w0.508: C27.1 71.57,23.21 71.57,22.46 72.24,21.79 C37.1
VDD_1: length 2.6
  TOP w0.254: U2.46 58.25,23.6 57.2,22.56 C28.1
VDD_2: length 3.5
  TOP w0.203: FB1.2 64.29,19.94 ; 64.62,20.68 U2.11
  TOP w0.508: 64.62,20.68 64.29,20.34 FB1.2 ; 64.29,19.94 64.29,18.92 C43.1
VDD_PLL: length 12.2
  TOP w0.254: v1(68.66,23.57) 68.66,23.52 68.08,24.1 U2.16
  TOP w0.508: C29.1 68.94,23.29 v1(68.66,23.57) ; C29.1 C38.1 ; C29.1 C33.1 ; v1(65.74,20.88) 65.76,20.85 FB1.1
  BOTTOM w0.762: v1(68.66,23.57) 68.66,22.3 68.28,21.92 66.78,21.92 v1(65.74,20.88)
VDD_REG_1V8: length 6.1
  TOP w0.203: C10.1 63.7,32.97 64.12,32.55 U2.27
  TOP w0.508: C10.1 64.82,33.6 C7.1
VDDIO: length 288.1
  TOP w0.203: U2.28 63.62,31.22 63.5,31.34 ; 52.48,22.35 52.96,21.87 RN3.4 ; 60.62,20.41 U2.3 ; v1(21.29,26.97) 21.39,26.97 21.74,26.63 U3.19
  TOP w0.254: v1(60.68,30.15) 60.62,30.09 U2.34 ; RN3.2 52.45,22.89 v1(52.43,22.86) ; 21.64,18.95 22.2,18.95 22.82,19.57 U3.32 ; v1(26.01,31.24) 26.33,30.93 U3.13 ; RN3.3 52.65,22.38 52.63,22.4 ; RN3.1 52.7,23.39 52.58,23.52
  TOP w0.305: 52.4,27.25 RN2.4 ; 52.86,28.27 RN2.2 ; RN2.3 52.65,27.76 ; RN2.1 52.81,28.78
  TOP w0.508: v1(63.12,32.18) 63.5,31.8 63.5,31.34 ; R47.2 41.02,21.34 v1(41.05,21.32) ; 21.64,18.95 C45.1 19.99,18.36 C46.1 18.62,18.36 18.19,18.8 18.19,20.98 v1(18.44,21.23) R60.2 ; 18.47,8.33 R68.2 ; 18.47,8.33 R69.2 ; 18.47,8.33 v1(18.41,8.38) ; v1(70.69,24.23) R33.2 ; R45.2 v1(61.59,16.1) 61.29,16.41 R42.2 60.33,17.98 60.27,18.03 ; R51.2 v1(41.05,19.69) ; R67.1 78.69,12.07 78.23,11.61 v1(78.23,10.97) R71.1 ; 60.27,18.03 v1(60.27,17.35) ; 60.27,18.03 C42.1 60.27,19.76 60.62,20.11 60.62,20.41 ; v1(60.68,30.15) 60.6,30.23 C19.1 ; v1(41.05,16.39) R55.1 ; v1(41.15,18.02) 41.2,18.02 41.22,18.04 R76.2 ; JP5.2 51.87,39.88 48.46,36.47 48.46,31.39 50.04,29.82 53.11,29.82 R53.2 ; R46.2 v1(18.44,25.5) ; v1(55.32,23.52) 55.32,23.67 55.27,23.72 55.27,24.69 R57.1 R56.1 ; R66.1 v1(41.15,13.08) ; R29.1 79.91,30.48 80.21,30.78 85.98,30.78 ; R54.2 v1(18.44,22.66) ; v1(21.29,26.97) 21.23,26.92 C26.1 ; 85.98,33.22 85.93,33.27 R15.1 R20.1 ; v1(41.03,14.75) 41.03,14.76 41.38,14.76 41.4,14.74 R59.1 ; v1(49.73,10.36) 48.82,9.45 R74.2 ; R70.1 v1(76.15,10.97) ; R48.2 v1(18.44,24.08) ; R4.1 v1(86.16,47.45)
  TOP w0.762: JP10.2 76.07,11.05 v1(76.15,10.97) ; JTAG1.1 JTAG1.2 85.32,37.08 85.98,36.42 85.98,14.1 82.85,10.97 v1(78.23,10.97)
  TOP w0.889: 46.18,24.89 45.54,25.53 JP7.1
  TOP w1.016: 58.37,16.81 58.27,16.71 57.51,17.48 54.31,17.48 v1(51.97,19.81) 46.99,24.79 46.99,24.89 46.18,24.89 ; JP10.2 70.64,11.05 69.09,9.5 57.56,9.5 55.42,11.63 51,11.63 v1(49.73,10.36)
  BOTTOM w0.508: v1(37.24,28.6) 37.08,28.45 v1(35.31,28.45) ; v1(18.41,10.03) v1(18.41,8.38)
  BOTTOM w0.635: v1(78.23,10.97) v1(76.15,10.97)
  BOTTOM w0.762: v1(52.17,27.53) v1(52.17,28.35) 53.04,28.35 54.05,29.36 57.56,29.36 58.34,30.15 v1(60.68,30.15) 62.71,32.18 v1(63.12,32.18) ; v1(41.15,18.02) 36,18.02 35.51,17.53 v1(34.7,17.53) ; v1(41.15,18.02) 41.15,17.17 41.05,17.07 v1(41.05,16.39) 41.05,14.78 v1(41.03,14.75) 41.03,13.2 v1(41.15,13.08) 48.97,13.08 49.73,12.32 v1(49.73,10.36) ; v1(41.15,18.02) 41.15,18.85 41.05,18.95 v1(41.05,19.69) v1(41.05,21.32) 41.06,21.34 41.76,21.34 44.2,23.77 JP7.1
  BOTTOM w1.016: v1(18.44,25.5) v1(18.44,24.08) v1(18.44,22.66) v1(18.44,21.23) ; v1(18.44,25.5) 19.81,25.5 v1(21.29,26.97) 21.29,28.97 23.56,31.24 v1(26.01,31.24) 32.41,31.24 v1(32.61,31.04) ; v1(18.44,25.5) 17.3,25.5 ISO1.4 ; v1(60.27,17.35) 60.35,17.35 v1(61.59,16.1) 63.3,16.1 64.72,14.68 64.72,13.61 65.74,12.6 69.44,12.6 73.51,16.66 73.51,19.56 70.69,22.38 v1(70.69,24.23)
  vias: v1(51.87,23.47) v1(81.74,51.56) v1(82.4,52.22)
VDDIO_FLASH: length 21.5
  TOP w0.305: R38.1 60.35,33.91 60.55,34.11 60.55,36.27 60.38,36.45 R75.1
  TOP w0.508: JP5.1 55.55,39.29 R40.1 ; C40.1 60.1,37.62 59.69,37.21 R75.1 59.05,36.45 58.85,36.25 U6.8 56.21,36.25 55.55,36.91 R40.1 ; U6.3 54.03,33.71 54.61,34.29 54.61,36.53 54.23,36.91 54.23,37.85 R40.1
8MHZ_MCO: length 47.5
  TOP w0.203: R43.1 65.63,16.87 62.87,14.1 v1(62.69,14.1) ; v1(32.05,10.41) 31.85,10.62 29.67,10.62 27.25,13.03 R62.2
  BOTTOM w0.203: v1(32.05,10.41) 35.56,6.91 39.69,6.91 41.92,9.14 56.08,9.14 56.77,9.83 56.77,11.2 59.66,14.1 v1(62.69,14.1)
/HOLD: length 9.5
  TOP w0.203: R75.2 U6.7 v1(55.88,34.98)
  BOTTOM w0.203: v1(55.88,34.98) 57.25,36.35 57.25,38.13 57.89,38.76 JP6.2
BIU/PHY_ACT: length 26.9
  TOP w0.203: U2.37 58.62,28.1 58.42,28.3 v1(58.42,28.65) 58.06,28.65 57.51,29.21 55.27,29.21 54.84,28.78 RN2.8 ; DL8.1 46.74,18.04 46.94,18.25 v1(46.94,18.29)
  BOTTOM w0.203: v1(46.94,18.29) 47.96,19.3 50.14,19.3 50.34,19.51 50.34,23.42 51.16,24.23 57.61,24.23 57.96,24.59 57.96,28.19 v1(58.42,28.65)
BOOT0/PHY_ACT: length 45.3
  TOP w0.203: U2.40 58.18,26.6 57.4,27.38 57,27.38 v1(56.95,27.33) 56.9,27.38 56.29,27.38 55.93,27.03 54.76,27.03 54.53,27.25 RN2.5 ; v1(33.02,24.13) 33.02,27.56 31.82,28.75 U3.2 ; JP13.1 48.62,17.92 v1(46.84,19.69) DL4.1 45.59,19.77 45.59,20.37 45.39,20.57 40.03,20.57 v1(38.61,22)
  BOTTOM w0.203: v1(38.61,22) 36.47,24.13 v1(33.02,24.13) ; v1(46.84,19.69) 48.01,20.86 48.01,22.96 50.5,25.45 54.46,25.45 56.39,27.38 56.9,27.38 v1(56.95,27.33)
BOOT1/TX_ON: length 40.7
  TOP w0.203: U3.3 31.33,27.15 v1(32.11,26.37) ; v1(46.79,20.68) 46.34,20.68 DL3.1 45.67,21.95 45.47,22.15 39.67,22.15 v1(37.9,23.93) ; RN2.6 54.74,27.76 55.07,27.43 55.68,27.43 v1(56.34,28.09) 56.49,28.24 57.15,28.24 58.29,27.1 U2.39
  BOTTOM w0.203: v1(32.11,26.37) 32.87,25.6 37.24,25.6 37.9,24.94 v1(37.9,23.93) ; v1(46.79,20.68) 47.56,21.45 47.56,23.13 50.29,25.86 54.25,25.86 55.83,27.43 55.83,27.58 v1(56.34,28.09)
BOOT_0: length 61.8
  TOP w0.203: U3.60 37.82,25.63 40.49,22.96 46.13,22.96 48.01,21.08 48.01,19.98 48.68,19.3 51.31,19.3 53.85,16.76 53.85,15.9 54.46,15.29 60.45,15.29 64.87,10.87 68.33,10.87 69.8,12.34 76.66,12.34 77.37,11.63 77.37,9.3 77.57,9.09 R71.2 80.01,9.09 80.87,8.23 80.87,6.07 JP11.2
BOOT_1: length 72.7
  TOP w0.203: U3.28 24.06,22.13 26.82,24.89 v1(30.53,24.89) ; v1(36.88,24.89) 37.95,24.89 40.28,22.56 45.92,22.56 47.6,20.88 47.6,19.81 48.56,18.85 51.16,18.85 53.44,16.56 53.44,15.7 54.25,14.88 60.25,14.88 64.67,10.46 68.49,10.46 69.97,11.94 76.35,11.94 76.91,11.38 76.91,9.3 76.71,9.09 R70.2 76.15,8.64 76.3,8.48 77.62,8.48 78.07,8.04 78.07,5.8 JP11.4
  BOTTOM w0.203: v1(36.88,24.89) v1(30.53,24.89)
CL: length 37.2
  TOP w0.203: C18.1 67.77,29.46 66.75,28.45 66.75,28.02 66.34,27.6 U2.23 ; C18.1 R17.1 ; C18.1 v1(68.53,31.19) ; R50.2 48.27,37.54 52.03,41.3 61.57,41.3 63.55,39.32 63.55,37.95 TP1.1
  BOTTOM w0.203: v1(68.53,31.19) 68.53,36.27 67.51,37.29 TP1.1
CL_SEL: length 12.5
  TOP w0.203: Q1.1 49.53,31.75 50.5,30.78 54.41,30.78 54.64,30.56 R53.1 55.32,29.87 55.58,29.62 58.52,29.62 59.31,28.83 U2.36
I2C/UART: length 48.1
  TOP w0.203: v1(25.33,28.19) U3.15 25.33,30.61 24.89,31.04 20.22,31.04 JP12.1 ; RN3.8 54.41,25.25 53.9,25.76 v1(53.9,26.52) 53.95,26.57 54.51,26.57 54.56,26.62 57.56,26.62 58.07,26.1 U2.41
  BOTTOM w0.203: v1(25.33,28.19) 25.33,28.17 26.52,26.97 27.79,26.97 28.65,27.84 33.43,27.84 34.9,29.31 45.97,29.31 48.87,26.42 52.98,26.42 53.14,26.57 53.85,26.57 v1(53.9,26.52)
J_TCK: length 68.8
  TOP w0.203: JTAG1.9 79.35,26.92 77.62,25.2 77.62,14.99 76.81,14.17 75.23,14.17 v1(75.18,14.12) ; U3.49 35.4,20.13 37.95,17.58 37.95,13.36 40.18,11.13 46.77,11.13 48.9,13.26 58.12,13.26 v1(59.33,12.04)
  BOTTOM w0.203: v1(59.33,12.04) 59.33,11.66 61.04,9.96 71.53,9.96 75.18,13.61 v1(75.18,14.12)
J_TDI: length 72.7
  TOP w0.203: JTAG1.5 80.21,32 79.65,31.45 R20.2 78.82,31.45 76.81,29.44 76.81,16.26 75.39,14.83 74.17,14.83 v1(73.63,14.3) ; U3.50 35.51,20.63 38.36,17.78 38.36,13.56 40.39,11.53 46.58,11.53 48.72,13.67 59.23,13.67 60.45,12.45 v1(60.45,11.56)
  BOTTOM w0.203: v1(60.45,11.56) 60.96,12.07 62.87,12.07 63.75,11.18 70.76,11.18 72.39,12.8 72.39,13.46 73.23,14.3 v1(73.63,14.3)
J_TDO: length 71.5
  TOP w0.203: v1(73.2,13.26) 73.71,12.75 76.96,12.75 77.7,13.49 78.66,13.49 R67.2 79.65,13.51 80.21,12.95 82.04,12.95 82.42,13.34 82.42,20.57 JTAG1.13 ; U3.55 35.07,23.13 36.07,22.12 36.07,20.68 38.76,17.98 38.76,13.77 40.59,11.94 46.39,11.94 48.52,14.07 59.84,14.07 61.32,12.6 v1(61.32,10.79)
  BOTTOM w0.203: v1(61.32,10.79) 61.32,11.35 61.52,11.56 62.71,11.56 63.5,10.77 71.07,10.77 73.1,12.8 73.1,13.16 v1(73.2,13.26)
J_TMS: length 75.2
  TOP w0.203: U3.46 31.33,19.05 31.43,19.15 35.1,19.15 37.14,17.12 37.14,12.95 39.78,10.31 47.35,10.31 48.21,11.18 49.02,11.18 50.29,12.45 56.29,12.45 v1(57.66,11.07) ; JTAG1.7 R29.2 78.36,29.46 77.22,28.32 77.22,15.65 v1(76.76,15.19)
  BOTTOM w0.203: v1(57.66,11.07) 57.91,11.33 59.05,11.33 60.83,9.55 71.73,9.55 76.76,14.58 v1(76.76,15.19)
J_TRSTN: length 77.8
  TOP w0.203: U3.56 35.2,23.63 36.58,22.25 36.58,20.78 39.17,18.19 39.17,14.02 40.84,12.34 46.2,12.34 46.22,12.36 48.34,14.48 60.05,14.48 62.43,12.09 v1(62.43,10.77) ; JTAG1.3 79.2,34.54 R15.2 78.88,34.29 77.6,33.01 77.6,30.91 76.4,29.72 76.4,16.87 v1(75.11,15.57)
  BOTTOM w0.203: v1(62.43,10.77) 62.89,10.77 63.3,10.36 71.32,10.36 74.37,13.41 74.37,14.83 v1(75.11,15.57)
M25_C: length 9.1
  TOP w0.203: U2.29 63.09,28.85 63.09,30.63 61.29,32.44 R38.2 59.13,32.44 58.93,32.64 58.93,33.5 58.72,33.71 U6.6
M25_D: length 16.7
  TOP w0.203: R40.2 v1(58.06,37.85) ; v1(55.88,33.99) 55.88,32.92 56.36,32.44 U6.5 57.61,32.41 57.61,31.9 57.81,31.7 61.42,31.7 62.62,30.5 U2.30
  BOTTOM w0.203: v1(55.88,33.99) 56.08,33.99 58.06,35.97 v1(58.06,37.85)
M25_Q: length 17.4
  TOP w0.203: U2.31 62.12,30.39 61.21,31.29 57.3,31.29 57,31.6 51.66,31.6 51.21,32.05 51.21,34.65 51.51,34.95 52.73,34.95 U6.2
M25_SN: length 20.5
  TOP w0.203: R39.2 U6.1 51.44,36.25 50.8,35.61 50.8,31.8 51.41,31.19 56.74,31.19 57.05,30.89 61.01,30.89 61.62,30.28 U2.32
N: length 46.6
  TOP w1.016: D4.1 9.53,55.19 CN1.1
  BOTTOM w1.27: CN1.1 9.53,53.87 10.97,52.43 18.54,52.43 v1(21.18,55.07) v1(22.15,55.07) 44.16,55.07 T1.4
PA_IN+: length 4.2
  TOP w0.203: U2.21 66.73,26.6 67.64,27.51 67.64,27.72 C23.2 R27.2
PA_IN-: length 10.6
  TOP w0.203: U2.22 66.6,27.1 67.21,27.71 67.21,28.3 68.28,29.36 68.28,29.92 69.67,31.32 R18.2 C12.2 C6.1 R13.2
PA_OUT: length 19.2
  TOP w0.203: 64.62,29.64 U2.26
  TOP w0.381: 64.62,29.64 64.62,31.98 65.74,33.1 65.74,33.99 TP2.1 67.39,35.13 68.02,34.49 C6.2 R13.1 R12.1 67.39,36.78
  TOP w1.016: 67.56,37.85 66.95,37.85 65.84,38.96 JP2.1
PLC_RESETN: length 46.5
  TOP w0.203: U2.10 64.12,21.32 63.35,20.55 C41.1 R44.2 R45.1 63.35,15.57 63.14,15.37 60.96,15.37 60.58,15.75 55.02,15.75 v1(54.66,16.1) ; v1(54.66,18.8) 54.15,18.8 44.88,28.07 JP7.2 ; v1(54.25,10.52) 54.23,10.49 54.23,2.58 SW5.1
  BOTTOM w0.203: v1(54.25,10.52) 54.66,10.92 v1(54.66,16.1) v1(54.66,18.8)
PLC_RESETN_UC: length 6.8
  TOP w0.203: JP8.1 40.61,28.07 37.69,30.99 R32.1
PLC_RXD: length 20.5
  TOP w0.203: U3.17 23.77,27.63 23.98,27.84 24.64,27.84 25.15,27.33 26.67,27.33 v1(27.13,27.79)
  BOTTOM w0.203: v1(27.13,27.79) 27.58,28.24 33.2,28.24 35.56,30.61 JP8.2
PLC_TXD: length 20.7
  TOP w0.203: v1(23.98,29.06) 23.98,29.42 24.18,29.63 U3.16
  BOTTOM w0.203: v1(23.98,29.06) 32.74,29.06 36.83,33.15 JP8.3
RESERVED1: length 5.8
  TOP w0.203: U2.44 57.93,24.6 57.51,24.18 56.24,24.18 56.03,23.98 56.03,23.11 55.73,22.81 54.81,22.81 54.74,22.89 RN3.7
RESERVED2: length 5.2
  TOP w0.203: U2.47 58.41,23.1 57.15,21.84 55.88,21.84 55.35,22.38 RN3.6
RESERVED3: length 5.1
  TOP w0.203: U2.48 58.57,22.6 57.4,21.44 55.68,21.44 55.24,21.87 RN3.5
RX_IN: length 27.6
  TOP w0.203: U2.19 70.94,25.6 73.1,27.76 TP6.1
  TOP w0.381: C20.1 78.69,39.73 v1(78.99,39.42)
  BOTTOM w0.508: v1(78.99,39.42) 78.99,29.26 77.5,27.76 TP6.1
RXD: length 24.2
  TOP w0.203: U2.2 60.12,21 v1(59.51,20.4) ; v1(58.01,20.4) 53.77,20.4 46.13,28.04 46.13,31.22 JP7.4
  BOTTOM w0.203: v1(59.51,20.4) v1(58.01,20.4)
SCL: length 31.8
  TOP w0.203: R56.2 v1(57.25,25.91) 57.56,25.6 U2.42 ; U3.61 37.9,26.13 40.66,23.37 46.33,23.37 48.46,21.23 48.46,20.73 v1(48.72,20.47)
  BOTTOM w0.203: v1(57.25,25.91) 55.52,25.91 54.66,25.04 50.75,25.04 48.72,23.01 v1(48.72,20.47)
SDA: length 32.5
  TOP w0.203: R57.2 57.2,24.89 v1(57.25,24.94) 57.41,25.1 U2.43 ; U3.62 37.97,26.63 40.82,23.77 46.53,23.77 49.58,20.73 v1(49.58,20.02)
  BOTTOM w0.203: v1(57.25,24.94) 55.17,24.94 54.86,24.64 50.95,24.64 49.58,23.27 v1(49.58,20.02)
SEC: length 11.1
  TOP w0.762: L2.2 61.42,50.72 60.66,49.96 JP1.2 58.52,47.29 58.38,47.15 T1A.1 54.83,47.15 54.78,47.2 T1.10
SPI2_MISO: length 58.1
  TOP w0.203: v1(32.72,7.87) 32.31,8.28 29.21,8.28 25.35,12.14 25.35,16.35 25.82,16.82 U3.35
  BOTTOM w0.203: v1(32.72,7.87) 34.09,6.5 39.9,6.5 42.14,8.74 68.94,8.74 69.85,7.82 69.85,5.84 J1.4
SPI2_MOSI: length 64
  TOP w0.203: U3.36 26.33,16.61 25.76,16.04 25.76,12.34 29.11,8.99 v1(29.67,8.99)
  BOTTOM w0.203: J1.2 71.53,2.44 62.13,2.44 61.37,3.2 61.37,5.38 60.05,6.71 43.28,6.71 41.05,4.47 31.6,4.47 29.21,6.86 29.21,8.59 29.62,8.99 v1(29.67,8.99)
SPI2_NSS: length 59.9
  TOP w0.203: U3.33 24.82,17.24 24.54,16.95 24.54,11.74 29.41,6.86 v1(30.89,6.86)
  BOTTOM w0.203: v1(30.89,6.86) 32.46,5.28 40.59,5.28 42.82,7.52 60.55,7.52 62.18,5.89 62.18,3.66 62.59,3.25 66.55,3.25 67.31,4.01 67.31,5.84 J1.5
SPI2_SCLK: length 58.1
  TOP w0.203: U3.34 25.33,17.03 24.94,16.65 24.94,11.94 29.06,7.82 29.72,7.82 v1(29.97,7.57)
  BOTTOM w0.203: v1(29.97,7.57) 29.97,6.73 31.83,4.88 40.82,4.88 43.05,7.11 60.3,7.11 61.77,5.64 61.77,3.45 62.38,2.84 66.85,2.84 J1.6
STM32_CFG0: length 26.2
  TOP w0.203: SW1.1 6.35,22.2 J2.5 17.88,26.21 20.22,26.21 20.37,26.06 R46.1 20.78,25.5 21.4,26.13 U3.20
STM32_CFG1: length 28.1
  TOP w0.203: U3.21 21.51,25.63 20.93,25.04 20.93,24.28 20.73,24.08 R48.1 20.37,24.59 20.17,24.79 17.93,24.79 15.49,22.35 15.49,21.29 J2.4 6.35,19.66 SW1.2
STM32_CFG2: length 30.2
  TOP w0.203: U3.22 21.82,25.13 21.34,24.64 21.34,23.11 20.88,22.66 R54.1 20.37,23.22 20.22,23.37 17.78,23.37 16.05,21.64 16.05,19.3 J2.3 11.99,17.12 10.72,15.85 5.08,15.85 SW1.3
STM32_CFG3: length 32.2
  TOP w0.203: U3.23 21.98,24.63 21.74,24.38 21.74,22.91 21.03,22.2 21.03,21.54 20.73,21.23 20.43,21.23 20.37,21.3 ; 20.37,21.3 20.37,21.74 20.17,21.95 17.53,21.95 16.66,21.08 16.66,17.37 J2.2 11.73,14.58 10.46,13.31 5.08,13.31 SW1.4 ; 20.37,21.3 R60.1
STM32_NRST: length 86.8
  TOP w0.203: v1(76.66,13.46) 76.71,13.46 78.03,14.78 78.03,18.9 78.44,19.3 JTAG1.15 ; v1(58.67,10.62) 58.67,11.63 57.45,12.85 49.63,12.85 v1(48.67,11.89) 48.31,11.89 47.14,10.72 39.98,10.72 37.54,13.16 37.54,17.37 35.36,19.56 33.02,19.56 32.21,20.37 32.21,25.25 29.33,28.13 U3.7 ; SW4.1 46.99,4.41 C50.1 R74.1 47.8,9.75 v1(48.46,10.41)
  BOTTOM w0.203: v1(58.67,10.62) 59.16,10.62 60.63,9.14 72.03,9.14 76.35,13.46 v1(76.66,13.46) ; v1(48.46,10.41) 48.46,11.68 v1(48.67,11.89)
STM32_USB+: length 5.5
  TOP w0.203: U3.45 30.82,15.66 31.5,14.99 R61.1 R58.1
STM32_USB-: length 5.5
  TOP w0.203: U3.44 30.33,15.55 31.45,14.43 31.45,14.12 31.8,13.77 R65.2
STPM_LED: length 50.7
  TOP w0.203: v1(31.95,9.09) 31.9,9.14 30.78,9.14 30.23,9.7 29.06,9.7 26.16,12.6 26.16,15.74 26.82,16.41 U3.37
  BOTTOM w0.203: v1(31.95,9.09) 32,9.04 32,7.54 33.45,6.1 40.13,6.1 42.37,8.33 64.82,8.33 J1.7
STPM_SYN: length 51.6
  TOP w0.203: v1(31.09,9.91) 30.89,10.11 29.26,10.11 26.57,12.8 26.57,15.44 27.33,16.2 U3.38
  BOTTOM w0.203: J1.8 64.82,5.79 62.89,5.79 60.76,7.92 42.6,7.92 40.36,5.69 33.22,5.69 31.09,7.82 v1(31.09,9.91)
T_REQ: length 23.6
  TOP w0.203: v1(50.8,27.23) 47.57,27.23 46.61,28.19 46.61,31.42 45.57,32.46 45.57,34.32 JP7.5 ; U2.38 58.4,27.6 57.2,28.8 55.98,28.8 v1(55.35,28.17) 55.27,28.24 54.43,28.24 RN2.7
  BOTTOM w0.203: v1(50.8,27.23) 51.21,26.82 52.73,26.82 54.08,28.17 v1(55.35,28.17)
T_REQ_UC: length 19.9
  TOP w0.203: JP8.4 38.33,32.36 v1(37.21,32.36) ; U3.14 25.82,28.79 v1(26.29,28.32)
  BOTTOM w0.203: v1(37.21,32.36) 36.68,32.36 32.97,28.65 26.62,28.65 v1(26.29,28.32)
TCK: length 3.4
  TOP w0.203: R42.1 61.29,19.51 62.62,20.84 U2.7
TX_OUT: length 7
  TOP w0.203: TP8.1 69.66,26.1 U2.20
  TOP w0.305: JP4.1 71.67,28.11 TP8.1
TXD: length 22.7
  TOP w0.203: U2.1 59.62,21.52 58.78,20.68 58.78,19.91 R41.1 55.6,19.13 55.02,19.71 53.85,19.71 45.72,27.84 45.72,29.08 JP7.3
USB_ID: length 13.5
  TOP w0.203: R64.2 30.81,13.94 31.7,13.06 33.63,13.06 34.14,12.55 v1(34.14,12.09) ; CN4.4 37.5,7.61 37.13,7.98 37.13,10.21 v1(37.24,10.31)
  BOTTOM w0.203: v1(34.14,12.09) 35.46,12.09 v1(37.24,10.31)
USB_VBUS: length 16
  TOP w0.203: U5.5 35.46,11.13 35.56,11.02 v1(35.56,10.92)
  TOP w0.508: 33.27,11.43 29.82,11.43 28.4,12.85 R63.2 ; 33.27,11.43 33.68,11.02 33.99,11.02 v1(34.14,10.87) 34.14,10.26 35.1,9.3 CN4.1 ; 33.27,11.43 C49.1
  BOTTOM w0.508: v1(34.14,10.87) 34.19,10.92 v1(35.56,10.92)
ZC_IN: length 95.3
  TOP w0.203: R30.2 71.7,25.22 71.58,25.1 U2.18 ; R30.2 74.37,25.22 TP11.1 74.63,25.48 76,26.82 76,29.97 77.06,31.04 77.06,31.95 75.84,33.17 74.27,33.17 71.53,35.92 71.53,36.63 70.31,37.85 v1(69.09,37.85) ; R30.2 R33.1 ; v1(64.36,38.86) 64.36,39.22 61.82,41.76 51.87,41.76 49.58,39.47 43.28,39.47 40.51,36.7 21.21,36.7 18.8,34.29 C15.1
  BOTTOM w0.203: v1(64.36,38.86) 65.38,37.85 v1(69.09,37.85)
N19516014: length 1.1
  TOP w0.203: DL3.2 R47.1
N19516015: length 1.1
  TOP w0.203: R51.1 DL4.2
N19516212: length 4.3
  TOP w0.762: JP1.1 61.19,45.24 R5.2 62.89,45.29 C2.2
N19516217: length 9.3
  TOP w1.016: D3.2 D2.1 65.94,48.08 C2.1 65.94,45.11 65.84,45.01 JP2.2
N19516236: length 2.1
  TOP w0.203: R18.1 C12.1 68.53,33.22 C13.2
N19516243: length 19.1
  TOP w0.508: v1(67.26,41.81) 68.12,41.81 D5.2 68.88,42.37 L3.2 75.03,42.37 75.74,43.08 C20.2 C11.2 ; R5.1 62.94,42.62 63.8,41.76 v1(64.72,41.76)
  BOTTOM w0.508: v1(64.72,41.76) 67.21,41.76 v1(67.26,41.81)
N19516257: length 4.1
  TOP w0.305: R27.1 R26.2 70.82,29.46 71.13,29.46 71.93,30.27 C22.2 71.93,30.28 71.28,30.93 71.27,30.93 R21.1
N19516279: length 4.7
  TOP w0.508: R6.2 4.57,44.07 ISO1.2 4.06,43.56 R7.1
N19516280: length 4.3
  TOP w0.508: ISO1.1 5.59,44.83 R6.1 6.17,45.59 R2.1
N19534232: length 2
  TOP w1.016: R1.1 R2.2
N19558802: length 3.5
  TOP w0.203: ISO1.3 4.32,35.94 R16.2 C15.2
N19595384: length 8.5
  TOP w0.203: U2.13 65.99,22.6 66.09,22.5 66.09,22.15 66.85,21.39 66.85,19 67.77,18.08 70.25,18.08 Y2.1
N19595391: length 10.5
  TOP w0.203: 67.21,14.23 67.72,14.73 67.72,17.53 66.6,18.64 R43.2 66.45,19.46 66.45,21.18 65.76,21.87 U2.12
N19717153: length 5.9
  TOP w0.203: CN4.3 36.7,7.54 36.47,7.77 36.47,11.28 35.96,11.79 U5.6
N19717271: length 6.1
  TOP w0.203: CN4.2 35.9,9.51 34.85,10.57 34.85,11.53 34.96,11.64 U5.4
N19719840: length 3.3
  TOP w0.203: R64.1 29.54,16.03 29.82,16.31 U3.43
N19719859: length 3.5
  TOP w0.203: U3.42 29.33,16.63 28.4,15.7 R63.1
N19719905: length 5.9
  TOP w0.203: U3.4 30.82,30.44 32.13,31.75 33.58,31.75 34.34,30.99 R32.2
N19719927: length 1.1
  TOP w0.203: R66.2 DL7.2
N19719929: length 1.1
  TOP w0.203: DL6.2 R59.2
N19719997: length 5.9
  TOP w0.203: U3.5 30.33,30.89 30.1,31.12 C25.1 30.1,33.5 29.49,34.11 Y1.2
N19720003: length 1.1
  TOP w0.203: DL5.2 R55.2
N19720009: length 9
  TOP w0.203: U3.6 29.82,30.63 29.21,31.24 C24.1 29.21,32.56 26.47,35.31 24.74,35.31 Y1.1
N19720046: length 29
  TOP w0.203: R68.1 v1(15.7,7.26) 15.7,3.72 SW2.1 ; v1(24.59,21.39) 24.35,21.63 U3.29
  BOTTOM w0.203: v1(15.7,7.26) 20.88,7.26 22.4,8.79 22.4,19.2 v1(24.59,21.39)
N19720048: length 21.9
  TOP w0.203: SW3.1 23.88,2.88 23.88,7.52 v1(23.06,8.33) R69.1 ; U3.30 23.78,21.13 24.28,20.62 v1(24.28,19.96)
  BOTTOM w0.203: v1(23.06,8.33) 22.81,8.59 22.81,18.49 v1(24.28,19.96)
N19720062: length 17
  TOP w0.203: DL5.1 45.67,17.02 45.42,17.27 40.69,17.27 40.44,17.53 40.44,18.85 37.85,21.44 37.85,22.89 35.61,25.13 U3.59
N19720066: length 18.1
  TOP w0.203: DL6.1 45.67,14.74 45.67,15.49 45.52,15.65 40.69,15.65 39.98,16.36 39.98,18.69 37.44,21.23 37.44,22.66 35.47,24.63 U3.58
N19720070: length 19.4
  TOP w0.203: U3.57 35.34,24.13 36.98,22.48 36.98,20.98 39.57,18.39 39.57,14.68 40.34,13.92 45.52,13.92 45.67,13.77 45.67,13.08 DL7.1
N19720108: length 3.8
  TOP w0.203: R62.1 27.25,15.37 28.82,16.94 U3.41
N19726409: length 1
  TOP w0.508: R3.2 DL1.2
N19726413: length 0.9
  TOP w0.508: R4.2 DL2.2
N19741938: length 2.3
  TOP w0.203: R52.1 79.63,14.68 80.09,14.22 JTAG1.19
N19741958: length 2.4
  TOP w0.203: JTAG1.17 80.49,17.42 R49.1
N19741995: length 2.2
  TOP w0.203: R34.1 JTAG1.11
N19742827: length 19.4
  TOP w0.508: J1.10 63.5,4.32 65.18,2.64 74.27,2.64 75.29,3.66 75.29,8.66 JP10.1
N19754973:
  vias: v1(78.84,54.71) v1(79.45,55.27)
N19761232: length 2
  TOP w0.305: C22.1 73.13,30.51 JP4.2
N19768553: length 1.6
  TOP w0.203: R65.1 34.89,13.77 U5.3
N19768555: length 4.3
  TOP w0.203: U5.1 35.96,14.99 35.41,15.54 34.65,15.54 34.09,14.99 R61.2
N19777479: length 1.6
  TOP w0.381: U4.3 76.34,35.17 76.4,35.1 C32.1
N19777489: length 6.9
  TOP w0.381: U4.1 73.91,35.92 73.74,35.74 R36.2 72.42,35.74 72.09,36.07 72.09,36.83 70.46,38.46 70.46,39.67 JP9.2
N19810275: length 1.1
  TOP w0.203: R76.1 DL8.2
N195512301: length 2.9
  TOP w1.016: R7.2 1.65,47.37 3.11,48.83 D4.2
N197853990: length 2.9
  TOP w0.203: R50.1 Q1.3

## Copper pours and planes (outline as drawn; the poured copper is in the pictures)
GND_FIELD SIGNAL on TOP: 67.01,23.7 67.01,23.19 67.64,22.56 67.64,20.65 68.02,20.27 69.67,20.27 70.31,20.9 70.31,21.54 69.55,21.54 69.55,20.9 69.42,20.78 68.4,20.78 68.28,20.9 68.28,22.94 67.51,23.7
GND_FIELD SIGNAL on TOP: 7.34,0.51 30.07,0.51 30.48,0.91 30.48,5.08 24.13,11.43 24.13,16.89 23.88,17.14 19.43,17.14 19.18,16.89 19.18,9.91 18.67,9.4 12.95,9.4 9.4,12.95 7.62,12.95 6.99,12.32 6.99,0.86
GND_FIELD SIGNAL on TOP: 67.01,33.58 66.29,33.58 66.29,33.02 65.1,31.83 65.1,29.54 64.97,29.41 64.97,28.52 65.1,28.4 65.35,28.65 65.35,29.03 66.19,29.87 66.19,30.63 66.5,30.94 67.01,30.94
GND_FIELD SIGNAL on TOP: 76.71,31.85 76.71,31.37 74.46,29.12 73.46,30.12 75.01,31.67 75.01,32.54 75.26,32.79 75.77,32.79
GND_FIELD SIGNAL on TOP: 77.06,56.03 74.78,58.32 71.53,58.32 70.71,57.51 70.71,56.29 68.3,53.87 68.3,53.44 60.07,53.44 59.82,53.7 54.08,53.7 53.47,54.31 53.47,59.56 77.9,59.56 80.92,56.54 80.92,55.93 83.39,53.47 84.45,53.47 84.71,53.21 86.77,53.21 86.77,44.96 67.87,44.96 67.87,47.8 68.28,48.21 73.05,48.21 76.15,51.31 76.15,52.91 76.33,53.09 76.91,53.09 77.06,53.24
GND_FIELD SIGNAL on TOP: 35.81,16.89 36.83,16.89 37.21,16.51 37.21,13.08 40.23,10.06 45.34,10.06 45.34,6.99 45.72,6.6 49.4,6.6 49.72,6.92 49.72,9.08 50.67,10.03 54.61,10.03 56.01,8.64 72.01,8.64 72.39,8.25 72.39,1.4 71.5,0.51 43.69,0.51 43.31,0.89 43.31,6.35 43.56,6.6 44.32,6.6 44.7,6.99 44.7,7.87 44.32,8.25 41.66,8.25 41.02,7.62 38.35,7.62 37.59,8.38 37.59,10.62 36.45,11.76 36.45,14.86 35.81,15.49
GND_FIELD SIGNAL on TOP: 61.9,34.37 64.08,34.37 64.41,34.7 65.3,34.7 65.6,34.99 65.6,35.62 66.5,36.53 66.5,37.34 65.79,37.34 64.41,35.97 63.4,35.97 63.04,36.32 60.96,36.32 60.96,34.44 61.82,34.44
GND_FIELD SIGNAL on TOP: 21.34,36.47 21.34,32.77 25.53,32.77 27.05,31.24 30.99,31.24 31.75,32 32.97,32 32.97,36.47
GND_FIELD SIGNAL on TOP: 70.33,20.68 72.44,20.68 73.66,19.46 73.66,17.22 67.56,11.13 65.13,11.13 64.11,12.14 64.11,14.78 66.34,17.02 66.34,19.05 66.97,19.67 66.24,20.4 66.24,22.94 66.88,22.94 67.51,22.3 67.51,20.52 68.02,20.02 69.67,20.02
GND_FIELD SIGNAL on BOTTOM: 87.88,34.7 87.88,0.51 0.51,0.51 0.51,36.83 40.39,36.83 43.18,39.62 49.48,39.62 51.77,41.91 60.2,41.91 62.33,39.78 62.33,36.22 62.69,35.86 63.96,35.86 64.21,35.61 64.21,34.24 63.96,33.99 63.96,28.85 64.01,28.8 64.21,28.8 64.26,28.85 64.26,34.04 64.47,34.24 64.47,35.66 64.11,36.02 62.79,36.02 62.48,36.32 62.48,39.88 60.33,42.04 60.33,42.8 56.81,46.32 56.81,50.61 53.47,53.95 53.47,59.56 65.18,59.56 65.18,55.12 67.67,52.63 71.32,52.63 72.03,51.92 72.03,50.55 73.25,49.33 76.96,49.33 79.25,47.04 79.25,44.25 76.61,41.61 75.08,41.61 72.34,38.86 71.78,38.86 70.05,37.13 70.05,34.95 70.51,34.49 72.54,34.49 76.4,38.35 79.4,38.35 79.6,38.15 79.6,17.22 78.99,16.61 74.27,16.61 74.27,16.41 79.15,16.41 79.86,17.12 79.86,35.26 80.37,35.76 86.82,35.76 ; 4 cut-outs
VCC on TOP: 74.57,54.97 74.57,53.24 74.73,53.09 75.54,53.09 75.69,52.93 75.69,51.56 75.06,50.93 71.37,50.93 70.36,51.94 70.36,54.97
VCC on TOP: 66.67,30.51 66.67,29.97 65.74,29.03 65.74,28.52 65.48,28.27 65.48,28.02 66.24,28.02 66.24,28.47 67.34,29.57 67.34,30.48 67.26,30.56 66.73,30.56
VCC on TOP: 69.42,37.13 70.46,37.13 71.17,36.42 71.17,35.81 73.76,33.22 72.67,32.13 72.67,32.03 71.93,31.29 70.89,32.33 70.56,32.33 70.21,32.69 70.21,36.22 70.03,36.4 69.42,36.4
VCC on BOTTOM: 72.34,53.04 72.34,50.6 73.36,49.58 77.06,49.58 79.5,47.14 79.5,44.15 76.71,41.35 75.23,41.35 72.49,38.61 71.88,38.61 70.31,37.03 70.31,35.05 70.61,34.75 72.49,34.75 83.62,45.87 83.62,48.46 78.87,53.21 72.52,53.21
VDDIO on TOP: 82.75,52.07 81.89,51.21 81.38,51.21 80.11,52.48 81.57,53.94 82.75,52.76
